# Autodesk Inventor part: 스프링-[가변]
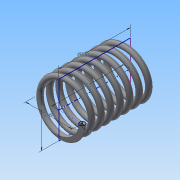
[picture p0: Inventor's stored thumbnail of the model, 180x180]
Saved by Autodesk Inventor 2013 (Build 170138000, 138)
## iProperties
Created: 2014-12
Part Number: 스프링-[가변]
Material: 일반
Document SubType Name: Modeling
Designer: Administrator
Density: 1 g/cm^3
Mass: 10.1763 g
Surface Area: 103.211 cm^2
Volume: 10.1763 cm^3
Author: Administrator
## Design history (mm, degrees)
sketch "스케치1"
  geometry: L1 (0, 0)-(0, 48.5); L2 (0, 0)-(17.5, 0); L3 (0, 48.5)-(17.5, 48.5); C1 r 2 at (17.5, 0)
  constraints: 6 end point, 1 centre point, 1 horizontal alignment, 1 parallel, 1 perpendicular, 1 vertical
  dimensions: "d0" = 48.5 distance of L1.start L1.end (derived); "d1" = 4 diameter of C1; "d2" = 35 diameter of L2.end L1
feature "코일1" sketch "스케치1" pitch "d3" = 10; turns "d5" = 7.5; dims "d4" = 48.5 (= d0), "d6" = 0, angle "d7" = 90 deg, angle "d8" = 90 deg, "d9" = 0, "d10" = 0
sketch "스케치2"
  geometry: L1 (48.5, -20)-(0, -20); L2 (0, -20)-(0, 20); L3 (0, 20)-(48.5, 20); L4 (48.5, 20)-(48.5, -20); 2 further points
  constraints: 8 end point, 2 parallel, 1 coincident, 1 horizontal, 1 midpoint, 1 perpendicular
  dimensions: "d11" = 48.5 distance of L2.end L3.end (derived); "d13" = 40 distance of L1.end L2.end
extrude "돌출1" sketch "스케치2" stored distance "d14" = 10; taper "d15" = 0 deg
node "솔리드1"
